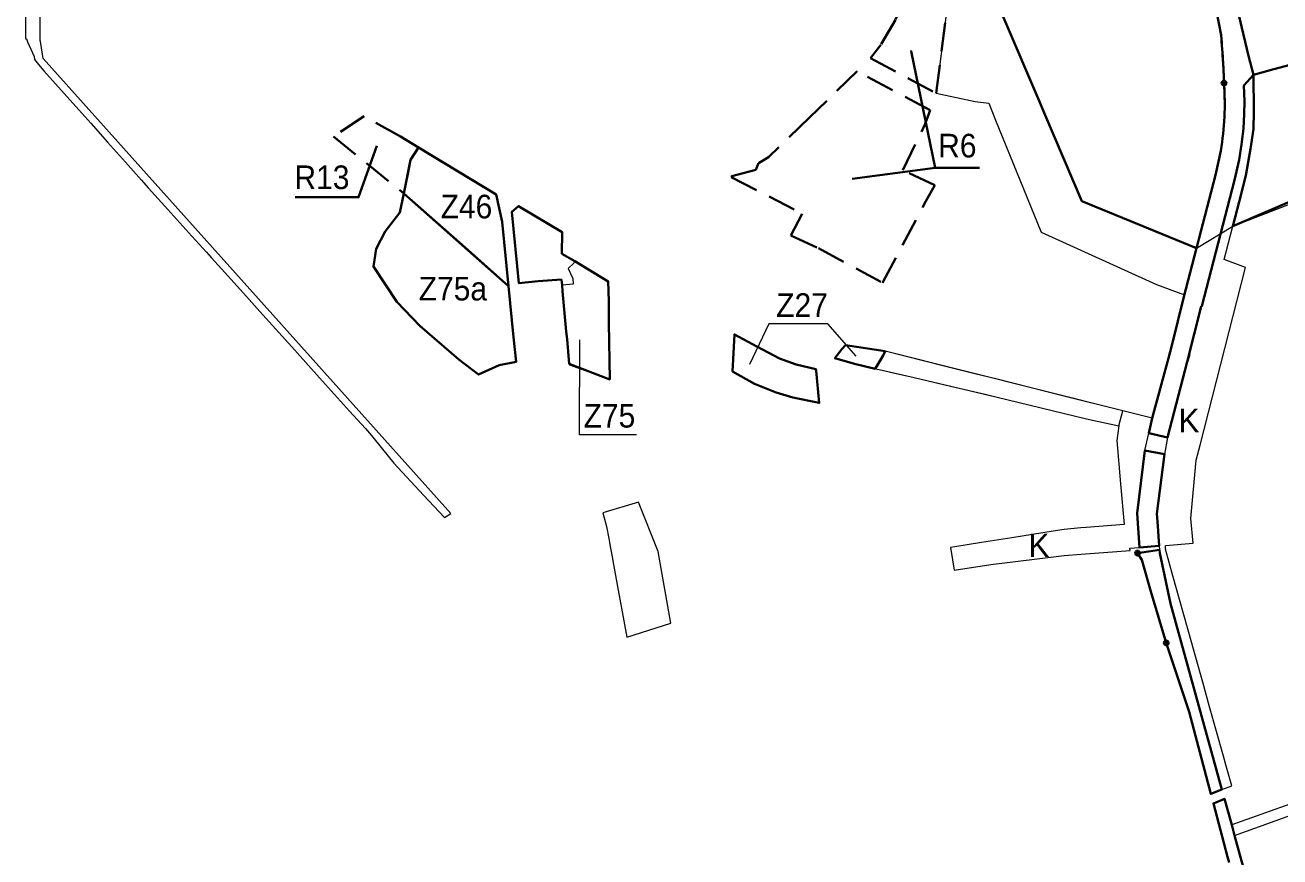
# Model space of a CAD drawing. Extents: x -650276 to -642489, y -1074311 to -1066658.
# Drawn here: x -650276 to -649001, y -1070697 to -1069852 of the extents above; entities that cross this region are included whole.
import ezdxf

# ---------------------------------------------------------------- set-up
doc = ezdxf.new("R2010")
doc.units = 0
doc.header["$LTSCALE"] = 9.6
doc.header["$PDMODE"] = 32
doc.header["$PDSIZE"] = 4.8
doc.linetypes.add('MEDIUM_DASHED', pattern=[4.5, 3, -1.5])
for name, color, linetype, lineweight in [('44', 7, 'Continuous', 40), ('45', 7, 'Continuous', 40), ('46', 7, 'Continuous', 13), ('47', 7, 'Continuous', 13), ('48', 7, 'Continuous', 13), ('61', 7, 'MEDIUM_DASHED', 40), ('62', 7, 'Continuous', 35), ('63', 7, 'Continuous', 13)]:
    doc.layers.add(name, color=color, linetype=linetype, lineweight=lineweight)

msp = doc.modelspace()

# ---------------------------------------------------------------- linework, layer by layer
at = {"layer": '44'}
for p, q in [((-649058.858, -1069889.759), (-649057.868, -1069910.51)), ((-649057.134, -1069932.873), (-649057.868, -1069910.51)), ((-649146.163, -1070347.543), (-649145.424, -1070357.637))]:
    msp.add_line(p, q, dxfattribs=at)
for points in [[(-649061.138, -1069979.243), (-649061.138, -1069979.243), (-649061.139, -1069979.254), (-649066.487, -1070004.267), (-649098.65, -1070127.795), (-649110.925, -1070177.113), (-649114.174, -1070189.816), (-649130.712, -1070250.935), (-649134.294, -1070266.095), (-649115.159, -1070270.568), (-649095.152, -1070193.731), (-649093.095, -1070186.132), (-649095.152, -1070193.731), (-649080.924, -1070137.409), (-649080.38, -1070136.996), (-649047.131, -1070009.304), (-649042.468, -1069988.477), (-649042.468, -1069988.477), (-649039.966, -1069973.035), (-649037.98, -1069956.626), (-649037.322, -1069942.129), (-649037.137, -1069928.996), (-649037.665, -1069912.977), (-649028.017, -1069902.109), (-649032.928, -1069882.782), (-649048, -1069820)], [(-649068, -1069825.147), (-649060.897, -1069861.994)], [(-649138.43, -1070283.6), (-649146.163, -1070347.543), (-649146.163, -1070347.543)], [(-649125.503, -1070355.837), (-649126.069, -1070348.097), (-649118.257, -1070287.455), (-649138.43, -1070283.6)], [(-649145.424, -1070357.637), (-649143.633, -1070382.123), (-649123.693, -1070380.572), (-649125.503, -1070355.837)], [(-649059.951, -1070628.223), (-649112.14, -1070439.152), (-649123.138, -1070388.16), (-649123.385, -1070384.775), (-649145.73, -1070387.91)], [(-649145.73, -1070387.91), (-649141.48, -1070394.84), (-649132.07, -1070426.81), (-649116.56, -1070479.19)], [(-649116.56, -1070479.19), (-649093.2, -1070549.1), (-649071.33, -1070632.6), (-649059.951, -1070628.223)], [(-649025.129, -1070754.377), (-649047.11, -1070674.743), (-649050.081, -1070663.981), (-649057.338, -1070637.689), (-649068.65, -1070642.23), (-649068.65, -1070642.23), (-649054.31, -1070696.44), (-649052.77, -1070702.25)]]:
    msp.add_lwpolyline(points, dxfattribs=at)
for centre, radius, start, end in [((-649633.43, -1069918.001), 575.266, 2.81398, 5.58706), ((-649347.129, -1069931.193), 290, 350.46253, 4.08974), ((-649347.129, -1069931.193), 290, 359.66809, 4.08974)]:
    msp.add_arc(centre, radius, start, end, dxfattribs=at)
for p in [(-649145.73, -1070387.91), (-649116.56, -1070479.19)]:
    msp.add_point(p, dxfattribs=at)
at = {"layer": '45'}
msp.add_line((-649057.868, -1069910.51), (-649058.82, -1069890.548), dxfattribs=at)
for points in [[(-649312.03, -1069773.33), (-649246.81, -1069926.27), (-649246.81, -1069926.27), (-649239.635, -1069943.094), (-649202.375, -1070030.469), (-649202.375, -1070030.469), (-649085.737, -1070078.201), (-649066.487, -1070004.267), (-649061.139, -1069979.254), (-649061.138, -1069979.243), (-649061.138, -1069979.243)], [(-649060.897, -1069861.994), (-649068, -1069825.147)], [(-648906.547, -1069869.711), (-649007.37, -1069896.602), (-649028.017, -1069902.109), (-649027.457, -1069939.468), (-649028.007, -1069957.455), (-649030.869, -1069977.253), (-649035.775, -1070004.354), (-649042.536, -1070031.342), (-649048.918, -1070055.852), (-648978.654, -1070025.669)], [(-649730.837, -1070084.028), (-649730.6, -1070061.98), (-649774.73, -1070035.58), (-649781.53, -1070041.2), (-649774.45, -1070113.92), (-649754.82, -1070111.89), (-649731.12, -1070109.96)], [(-649730.837, -1070084.028), (-649730.6, -1070061.98), (-649774.73, -1070035.58), (-649781.53, -1070041.2), (-649774.45, -1070113.92), (-649754.82, -1070111.89), (-649731.12, -1070109.96)], [(-649731.12, -1070109.96), (-649730.57, -1070115.76), (-649730, -1070122.01), (-649726.22, -1070162.75), (-649725.49, -1070170.64), (-649723.17, -1070195.81), (-649682.04, -1070211.58), (-649683.12, -1070154.14), (-649682.98, -1070132.1), (-649683.57, -1070112.05), (-649717.72, -1070091.61), (-649730.837, -1070084.028)], [(-649731.12, -1070109.96), (-649730.57, -1070115.76), (-649730, -1070122.01), (-649726.22, -1070162.75), (-649725.49, -1070170.64), (-649723.17, -1070195.81), (-649682.04, -1070211.58), (-649683.12, -1070154.14), (-649682.98, -1070132.1), (-649683.57, -1070112.05), (-649717.72, -1070091.61), (-649730.837, -1070084.028)]]:
    msp.add_lwpolyline(points, dxfattribs=at)
for points in [[(-649891.21, -1070022.68), (-649832.007, -1070074.751), (-649784.87, -1070116.76), (-649791.31, -1070051.51), (-649797.45, -1070023.77), (-649876.31, -1069975.93), (-649884.59, -1069988.57)], [(-649891.21, -1070022.68), (-649832.007, -1070074.751), (-649784.87, -1070116.76), (-649791.31, -1070051.51), (-649797.45, -1070023.77), (-649876.31, -1069975.93), (-649884.59, -1069988.57)], [(-649891.21, -1070022.68), (-649895.45, -1070042.15), (-649910.34, -1070061.29), (-649919.55, -1070079.01), (-649922.3, -1070096.9), (-649898.55, -1070132.9), (-649874.94, -1070157.19), (-649835.28, -1070191.27), (-649815.33, -1070206.63), (-649794.37, -1070197.2), (-649777.29, -1070193.57), (-649779.75, -1070168.69), (-649784.87, -1070116.76)], [(-649557.21, -1070203.53), (-649555.44, -1070165.91), (-649532.57, -1070178.08), (-649509.72, -1070190.24), (-649492.67, -1070196.34), (-649472.6, -1070201.15), (-649472.43, -1070202.9), (-649469.176, -1070235.365), (-649496, -1070230), (-649513, -1070225), (-649535, -1070216)], [(-649557.21, -1070203.53), (-649555.44, -1070165.91), (-649532.57, -1070178.08), (-649509.72, -1070190.24), (-649492.67, -1070196.34), (-649472.6, -1070201.15), (-649472.43, -1070202.9), (-649469.176, -1070235.365), (-649496, -1070230), (-649513, -1070225), (-649535, -1070216)], [(-649442.63, -1070176.69), (-649402.29, -1070182.92), (-649404.2, -1070187.43), (-649412.2, -1070200.71), (-649433.3, -1070195.89), (-649453.27, -1070190.02), (-649446.19, -1070180.76)], [(-649442.63, -1070176.69), (-649402.29, -1070182.92), (-649404.2, -1070187.43), (-649412.2, -1070200.71), (-649433.3, -1070195.89), (-649453.27, -1070190.02), (-649446.19, -1070180.76)]]:
    msp.add_lwpolyline(points, close=True, dxfattribs=at)
for centre, radius, start, end in [((-649649.71, -1069919.176), 591.583, 2.77379, 5.54687), ((-649347.129, -1069931.193), 290, 350.46253, 4.08974)]:
    msp.add_arc(centre, radius, start, end, dxfattribs=at)
msp.add_point((-649057.868, -1069910.51), dxfattribs=at)
at = {"layer": '46'}
for points in [[(-649431.69, -1070187.9), (-649460.604, -1070155.007), (-649520.489, -1070155.007), (-649540.207, -1070196.319)], [(-649654.738, -1070267.746), (-649712.819, -1070267.746), (-649712.819, -1070267.746), (-649712.586, -1070171.248)]]:
    msp.add_lwpolyline(points, dxfattribs=at)
at = {"layer": '47'}
msp.add_line((-649115.159, -1070270.568), (-649118.257, -1070287.455), dxfattribs=at)
for points in [[(-649538.49, -1069541.54), (-649527.84, -1069552.16), (-649517.81, -1069563.27), (-649507.23, -1069573.85), (-649474.46, -1069613.59), (-649415.12, -1069685.26), (-649401.77, -1069701.47), (-649392.85, -1069713.53), (-649385.25, -1069726.48), (-649379.49, -1069740.04), (-649376.01, -1069754.58), (-649372.2, -1069772.58), (-649370.94, -1069787.45), (-649372.56, -1069802.33), (-649372.56, -1069802.33), (-649338, -1069822), (-649350.222, -1069920.873), (-649310.738, -1069929.342), (-649296.851, -1069931.092)], [(-649202.375, -1070030.469), (-649239.635, -1069943.094), (-649246.81, -1069926.27), (-649246.81, -1069926.27), (-649312.03, -1069773.33), (-649364.44, -1069650.55), (-649379.32, -1069615.71)], [(-650270.059, -1069739.232), (-650269.449, -1069762.714), (-650276.214, -1069796.532), (-650275.76, -1069865.474), (-650274.95, -1069865.62)], [(-650260.665, -1069868.303), (-650260.748, -1069867.327), (-650261.204, -1069797.969), (-650254.411, -1069764.006), (-650255.21, -1069733.253), (-650255.716, -1069731.162), (-650259.97, -1069732.29), (-650264.91, -1069735.69), (-650270.059, -1069739.232)], [(-650274.95, -1069865.62), (-650273.61, -1069868.62), (-650266.89, -1069883.7)], [(-650266.89, -1069883.7), (-650266.68, -1069886.78), (-650262.64, -1069891.57), (-650257.16, -1069898.07), (-650224.71, -1069934.41), (-650209.51, -1069951.43), (-650192.51, -1069970.47), (-650174.3, -1069990.86), (-650157.87, -1070009.26), (-650151.03, -1070016.84), (-650134.26, -1070035.45), (-650106.76, -1070065.96), (-650091.89, -1070082.46), (-650087.18, -1070087.68), (-650076.72, -1070099.29), (-650051.33, -1070127.45), (-650037.78, -1070142.48), (-650018.41, -1070163.97), (-650005.3, -1070178.51), (-649990.95, -1070194.43), (-649977.05, -1070209.85), (-649946.39, -1070243.87), (-649930.46, -1070261.54), (-649924.15, -1070268.55), (-649913.03, -1070282.44), (-649901.59, -1070296.73), (-649871.28, -1070329.01), (-649850.04, -1070351.64), (-649843.513, -1070347.685), (-650257.713, -1069885.547), (-650260.665, -1069868.303)], [(-649057.722, -1070089.665), (-649048.918, -1070055.852), (-649037.411, -1070011.659), (-649032.972, -1069991.835), (-649028.007, -1069957.455), (-649027.566, -1069943.013), (-649027.135, -1069928.902), (-649027.569, -1069915.721), (-649028.017, -1069902.109), (-649037.665, -1069912.977), (-649037.137, -1069928.996), (-649037.199, -1069933.38), (-649037.322, -1069942.129), (-649037.98, -1069956.626), (-649039.623, -1069970.202), (-649042.468, -1069988.477), (-649047.131, -1070009.304), (-649055.689, -1070042.169), (-649061.354, -1070063.169), (-649067.061, -1070085.844), (-649079.268, -1070132.727), (-649080.38, -1070136.996), (-649080.872, -1070137.37), (-649083.089, -1070145.979)], [(-649296.851, -1069931.092), (-649289.95, -1069948.146), (-649243.846, -1070062.071), (-649126.437, -1070115.217), (-649126.437, -1070115.217), (-649098.101, -1070125.688), (-649085.737, -1070078.201), (-649202.375, -1070030.469)], [(-649089.07, -1070377.88), (-649091.46, -1070352.73), (-649086.157, -1070293.589), (-649082.233, -1070278.265), (-649036.031, -1070097.854), (-649057.722, -1070089.665)], [(-649083.089, -1070145.979), (-649095.152, -1070193.731), (-649093.095, -1070186.132), (-649095.152, -1070193.731), (-649111.303, -1070255.758), (-649095.152, -1070193.731), (-649115.159, -1070270.568)], [(-649118.257, -1070287.455), (-649126.069, -1070348.097), (-649125.503, -1070355.837), (-649123.693, -1070380.572)], [(-649123.693, -1070380.572), (-649123.385, -1070384.775), (-649123.138, -1070388.16), (-649112.14, -1070439.152), (-649059.951, -1070628.223), (-649049.96, -1070624.38), (-649055.93, -1070603.08), (-649058.38, -1070594.33), (-649065.42, -1070569.21), (-649072.47, -1070544.09), (-649079.51, -1070518.97), (-649086.55, -1070493.85), (-649093.59, -1070468.73), (-649100.01, -1070445.82), (-649102.31, -1070437.61), (-649109.76, -1070411.05), (-649117.36, -1070383.93), (-649117.374, -1070380.081), (-649089.07, -1070377.88)]]:
    msp.add_lwpolyline(points, dxfattribs=at)
for points in [[(-649159.19, -1070358.82), (-649197.91, -1070361.8), (-649203.4, -1070362.23), (-649220.47, -1070363.94), (-649231.39, -1070365.69), (-649273.57, -1070372.44), (-649304.18, -1070377.35), (-649331.3, -1070381.69), (-649335.79, -1070382.41), (-649332.2, -1070405.42), (-649294.79, -1070399.65), (-649269.769, -1070396.502), (-649220.16, -1070390.26), (-649202.969, -1070388.965), (-649153.11, -1070385.21), (-649153.64, -1070382.9), (-649143.633, -1070382.123), (-649146.163, -1070347.543), (-649138.43, -1070283.6), (-649134.294, -1070266.095), (-649130.712, -1070250.935), (-649160.748, -1070243.413), (-649220.52, -1070228.443), (-649288.379, -1070211.449), (-649310.998, -1070205.784), (-649342.149, -1070197.982), (-649402.29, -1070182.92), (-649404.2, -1070187.43), (-649412.2, -1070200.71), (-649408.24, -1070201.62), (-649391.184, -1070205.516), (-649372.69, -1070209.74), (-649335.914, -1070218.359), (-649299.227, -1070226.958), (-649289.83, -1070229.16), (-649197.55, -1070251.65), (-649164.91, -1070258.55), (-649166.86, -1070273.48), (-649162.91, -1070317.47)], [(-649014.888, -1070782.994), (-648966.35, -1070764.7), (-648908.94, -1070740.19), (-648892.215, -1070733.293), (-648927.2, -1070637.98), (-648941.064, -1070599.735), (-648965.569, -1070610.382), (-648956.687, -1070630.825), (-649050.081, -1070663.981), (-649047.11, -1070674.743), (-648952.455, -1070640.564), (-648922.196, -1070710.207), (-648924.668, -1070712.022), (-648943.837, -1070720.104), (-649025.129, -1070754.377)]]:
    msp.add_lwpolyline(points, close=True, dxfattribs=at)
at = {"layer": '61'}
for points in [[(-649372.56, -1069802.33), (-649379.19, -1069820.24), (-649391.86, -1069846.18), (-649406.53, -1069871.59), (-649417.234, -1069885.193), (-649350.222, -1069920.873), (-649338, -1069822)], [(-649430.515, -1069898.514), (-649479.08, -1069945.53), (-649520.6, -1069985.72), (-649530.31, -1069991.5), (-649530.99, -1069991.9), (-649533.61, -1069998.6), (-649557.92, -1070005.19), (-649558.56, -1070006.13), (-649486.5, -1070043.26), (-649497.95, -1070065.49), (-649469.85, -1070078.3), (-649404.76, -1070113.41), (-649360.74, -1070030.35), (-649351.66, -1070014.26), (-649384.249, -1069998.959), (-649361.46, -1069951.93), (-649356.458, -1069937.945)], [(-649931.76, -1069944.31), (-649962.859, -1069964.896), (-649891.21, -1070022.68), (-649884.59, -1069988.57), (-649876.31, -1069975.93), (-649894.68, -1069964.78)]]:
    msp.add_lwpolyline(points, close=True, dxfattribs=at)
at = {"layer": '62'}
for points in [[(-649306.343, -1069996.537), (-649351.328, -1069996.537), (-649375.864, -1069878.046), (-649351.328, -1069996.537), (-649435.663, -1070007.798)], [(-650001.823, -1070026.616), (-649937.373, -1070026.616), (-649918.861, -1069974.471)]]:
    msp.add_lwpolyline(points, dxfattribs=at)
at = {"layer": '62', "lineweight": 13}
msp.add_lwpolyline([(-650001.823, -1070026.616), (-649937.373, -1070026.616), (-649918.861, -1069974.471)], dxfattribs=at)
at = {"layer": '63'}
for points in [[(-649329.217, -1069733.065), (-649246.81, -1069926.27), (-649246.81, -1069926.27)], [(-649239.635, -1069943.094), (-649202.375, -1070030.469), (-649085.737, -1070078.201), (-649048.918, -1070055.852), (-648767.83, -1069946.87), (-648562.242, -1069870.301), (-648502.048, -1069957.969)], [(-649246.81, -1069926.27), (-649239.635, -1069943.094), (-649239.635, -1069943.094)], [(-649876.31, -1069975.93), (-649884.59, -1069988.57), (-649891.21, -1070022.68), (-649784.87, -1070116.76)], [(-649784.87, -1070116.76), (-649791.31, -1070051.51), (-649797.45, -1070023.77), (-649853.14, -1069989.98), (-649858.12, -1069986.96), (-649876.31, -1069975.93), (-649876.31, -1069975.93)], [(-649718.71, -1070093.35), (-649724.36, -1070099.03), (-649719.69, -1070108.94), (-649719.24, -1070114.87), (-649730.57, -1070115.76), (-649730, -1070122.01), (-649726.22, -1070162.75), (-649725.49, -1070170.64), (-649724.92, -1070176.78), (-649723.17, -1070195.81)], [(-649683.12, -1070154.14), (-649683.09, -1070148.44), (-649682.98, -1070132.1), (-649683.57, -1070112.05), (-649704.42, -1070099.48), (-649717.72, -1070091.61), (-649718.71, -1070093.35)], [(-649723.08, -1070196.73), (-649682.04, -1070211.58), (-649683.12, -1070154.14)], [(-649469.176, -1070235.365), (-649472.43, -1070202.9), (-649472.6, -1070201.15), (-649492.67, -1070196.34), (-649509.72, -1070190.24), (-649532.57, -1070178.08), (-649555.44, -1070165.91), (-649555.15, -1070169.51), (-649557.21, -1070203.53)], [(-649402.29, -1070182.92), (-649442.63, -1070176.69), (-649446.19, -1070180.76), (-649453.27, -1070190.02), (-649433.3, -1070195.89), (-649412.2, -1070200.71), (-649408.24, -1070201.62), (-649372.69, -1070209.74)], [(-649164.91, -1070258.55), (-649160.748, -1070243.413), (-649402.29, -1070182.92)], [(-649723.17, -1070195.81), (-649723.17, -1070195.81), (-649723.08, -1070196.73)], [(-649557.21, -1070203.53), (-649535, -1070216), (-649526.777, -1070219.364), (-649513, -1070225), (-649513, -1070225)], [(-649372.69, -1070209.74), (-649372.69, -1070209.74), (-649289.83, -1070229.16), (-649197.55, -1070251.65), (-649164.91, -1070258.55)], [(-649513, -1070225), (-649496, -1070230), (-649469.176, -1070235.365)], [(-649664.82, -1070473.32), (-649620.17, -1070459.09), (-649633, -1070386.46), (-649653.03, -1070336.2), (-649689.02, -1070346.94)], [(-649689.02, -1070346.94), (-649685.31, -1070360.88), (-649683.08, -1070373.11), (-649681.29, -1070382.89), (-649679.37, -1070393.37), (-649678.92, -1070395.81), (-649672.83, -1070429.29)], [(-649672.83, -1070429.29), (-649672.49, -1070431.16), (-649664.82, -1070473.32)]]:
    msp.add_lwpolyline(points, dxfattribs=at)

# ---------------------------------------------------------------- texts
at = {"layer": '46', "width": 0.95}
for s, p in [('Z46', (-649853.994, -1070048.002)), ('Z46', (-649853.994, -1070048.002)), ('Z75a', (-649876.242, -1070131.383)), ('Z27', (-649512.965, -1070148.029)), ('Z75', (-649708.673, -1070260.465))]:
    msp.add_text(s, height=24, dxfattribs=at).set_placement(p)
at = {"layer": '48'}
for p in [(-649104.211, -1070265.34), (-649256.486, -1070392.051)]:
    msp.add_text('K', height=24, dxfattribs=at).set_placement(p)
at = {"layer": '62', "width": 0.95}
for s, p in [('R6', (-649348.349, -1069986.108)), ('R13', (-650002.521, -1070018.261)), ('R13', (-650002.521, -1070018.261))]:
    msp.add_text(s, height=24, dxfattribs=at).set_placement(p)

doc.saveas('drawing.dxf')
